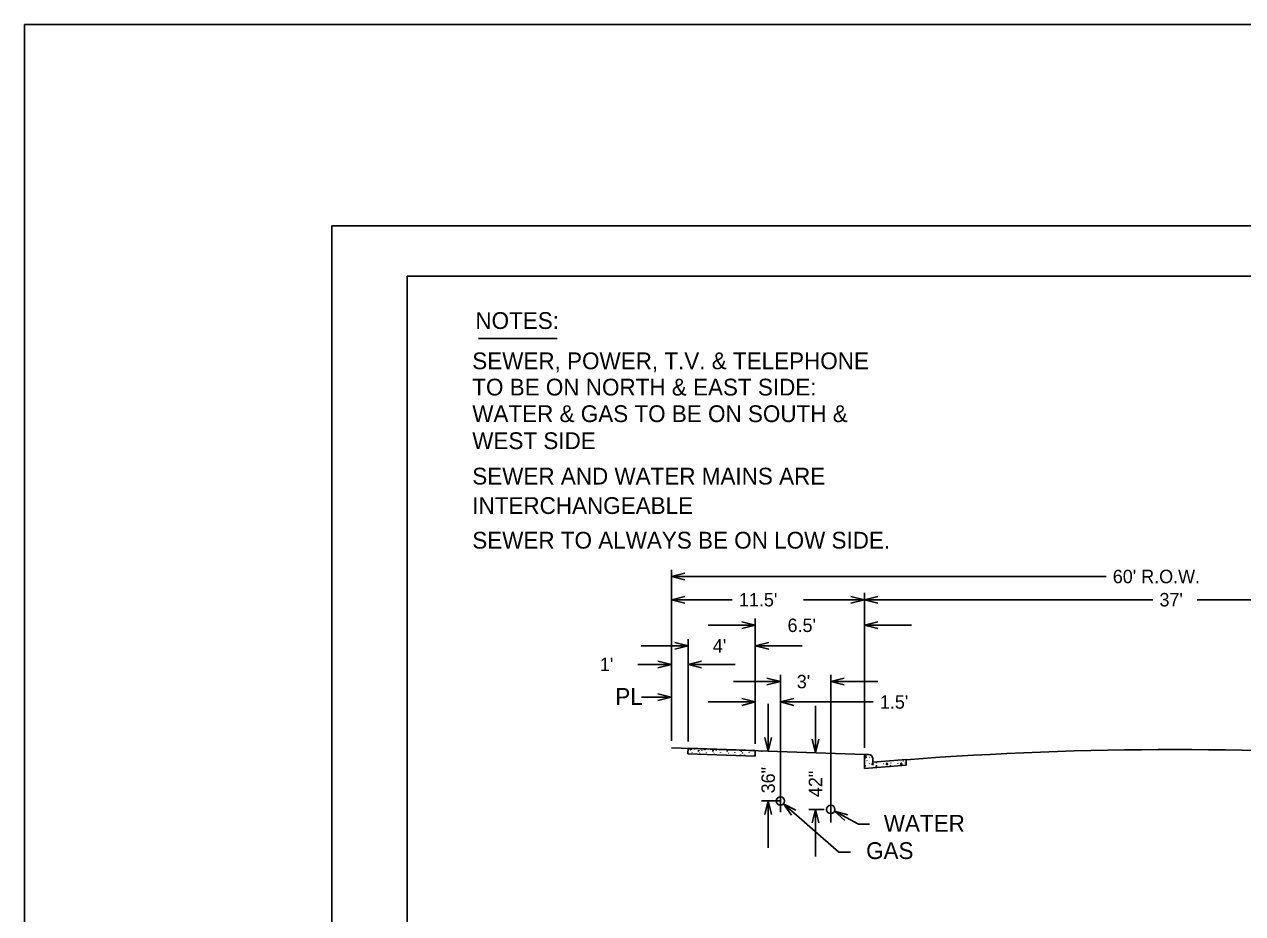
# Model space of a CAD drawing. Extents: x 524397 to 525117, y 3701341 to 3701821.
# Drawn here: x 524396.8 to 524541.9, y 3701715 to 3701821 of the extents above; entities that cross this region are included whole.
import ezdxf

# ---------------------------------------------------------------- set-up
doc = ezdxf.new("R2010")
doc.units = 0
for name, color, linetype in [('Level 1', 7, 'Continuous'), ('Level 11', 7, 'Continuous'), ('Level 9', 7, 'Continuous'), ('Pam batch print border', 7, 'Continuous')]:
    doc.layers.add(name, color=color, linetype=linetype)

msp = doc.modelspace()

# ---------------------------------------------------------------- linework, layer by layer
at = {"layer": 'Level 1'}
for p, q in [((524433.4, 3701796.98), (524433.4, 3701796.98)), ((524442.4, 3701790.98), (524442.4, 3701370.98)), ((524442.4, 3701790.98), (525097.4, 3701790.98))]:
    msp.add_line(p, q, dxfattribs=at)
at = {"layer": 'Level 11'}
for p, q in [((524450.88, 3701783.55), (524460.27, 3701783.55)), ((524473.87, 3701735.57), (524473.87, 3701755.98)), ((524473.87, 3701755.18), (524475.47, 3701755.58)), ((524525.66, 3701755.18), (524473.87, 3701755.18)), ((524475.47, 3701754.78), (524473.87, 3701755.18)), ((524473.87, 3701735.57), (524473.87, 3701753.21)), ((524473.87, 3701752.41), (524475.47, 3701752.81)), ((524481.12, 3701752.41), (524473.87, 3701752.41)), ((524475.47, 3701752.01), (524473.87, 3701752.41)), ((524489.61, 3701752.41), (524496.86, 3701752.41)), ((524495.26, 3701752.81), (524496.86, 3701752.41)), ((524496.86, 3701752.41), (524495.26, 3701752.01)), ((524496.86, 3701734.77), (524496.86, 3701753.21)), ((524496.86, 3701752.41), (524498.46, 3701752.81)), ((524531.22, 3701752.41), (524496.86, 3701752.41)), ((524498.46, 3701752.01), (524496.86, 3701752.41)), ((524536.52, 3701752.41), (524570.88, 3701752.41)), ((524478.26, 3701749.36), (524483.86, 3701749.36)), ((524482.26, 3701749.76), (524483.86, 3701749.36)), ((524483.86, 3701749.36), (524482.26, 3701748.96)), ((524483.86, 3701735.22), (524483.86, 3701750.16)), ((524496.86, 3701734.77), (524496.86, 3701750.16)), ((524496.86, 3701749.36), (524498.46, 3701749.76)), ((524496.86, 3701749.36), (524498.46, 3701749.76)), ((524502.46, 3701749.36), (524496.86, 3701749.36)), ((524498.46, 3701748.96), (524496.86, 3701749.36)), ((524498.46, 3701748.96), (524496.86, 3701749.36)), ((524475.87, 3701735.5), (524475.87, 3701747.71)), ((524483.86, 3701735.22), (524483.86, 3701747.71)), ((524470.27, 3701746.91), (524475.87, 3701746.91)), ((524474.27, 3701747.31), (524475.87, 3701746.91)), ((524475.87, 3701746.91), (524474.27, 3701746.51)), ((524483.86, 3701746.91), (524485.47, 3701747.31)), ((524489.47, 3701746.91), (524483.86, 3701746.91)), ((524485.47, 3701746.51), (524483.86, 3701746.91)), ((524469.87, 3701744.7), (524473.87, 3701744.7)), ((524472.27, 3701745.1), (524473.87, 3701744.7)), ((524473.87, 3701744.7), (524472.27, 3701744.3)), ((524473.87, 3701735.57), (524473.87, 3701745.5)), ((524475.87, 3701735.5), (524475.87, 3701745.5)), ((524475.87, 3701744.7), (524477.47, 3701745.1)), ((524481.47, 3701744.7), (524475.87, 3701744.7)), ((524477.47, 3701744.3), (524475.87, 3701744.7)), ((524486.86, 3701743.45), (524486.86, 3701727.1)), ((524486.86, 3701743.39), (524486.86, 3701743.45)), ((524492.86, 3701743.45), (524492.86, 3701725.84)), ((524481.26, 3701742.65), (524486.86, 3701742.65)), ((524485.26, 3701743.05), (524486.86, 3701742.65)), ((524486.86, 3701742.65), (524485.26, 3701742.25)), ((524492.86, 3701742.65), (524494.47, 3701743.05)), ((524498.47, 3701742.65), (524492.86, 3701742.65)), ((524494.47, 3701742.25), (524492.86, 3701742.65)), ((524492.86, 3701741.98), (524492.86, 3701741.85)), ((524473.86, 3701740.79), (524470.3, 3701740.79)), ((524472.26, 3701741.19), (524473.86, 3701740.79)), ((524473.86, 3701740.79), (524472.26, 3701740.39)), ((524482.26, 3701740.62), (524483.86, 3701740.22)), ((524483.86, 3701735.22), (524483.86, 3701741.02)), ((524486.86, 3701740.82), (524486.86, 3701741.02)), ((524486.86, 3701740.22), (524488.47, 3701740.62)), ((524478.26, 3701740.22), (524483.86, 3701740.22)), ((524483.86, 3701740.22), (524482.26, 3701739.82)), ((524485.4, 3701739.98), (524485.4, 3701734.37)), ((524497.91, 3701740.22), (524486.86, 3701740.22)), ((524488.47, 3701739.82), (524486.86, 3701740.22)), ((524491.04, 3701739.78), (524491.04, 3701734.17)), ((524485.4, 3701734.37), (524485, 3701735.97)), ((524485.8, 3701735.97), (524485.4, 3701734.37)), ((524496.86, 3701733.97), (524473.87, 3701734.77)), ((524475.87, 3701734.7), (524475.85, 3701734.04)), ((524483.86, 3701734.42), (524475.87, 3701734.7)), ((524476.66, 3701734.57), (524476.64, 3701734.6)), ((524478.36, 3701734.57), (524478.34, 3701734.6)), ((524491.04, 3701734.17), (524490.64, 3701735.77)), ((524491.44, 3701735.77), (524491.04, 3701734.17)), ((524475.85, 3701734.04), (524483.86, 3701733.76)), ((524476.33, 3701734.16), (524476.32, 3701734.19)), ((524477.26, 3701734.15), (524477.24, 3701734.13)), ((524477.27, 3701734.16), (524477.26, 3701734.14)), ((524477.51, 3701734.48), (524477.51, 3701734.45)), ((524478.04, 3701734.16), (524478.02, 3701734.19)), ((524478.96, 3701734.15), (524478.94, 3701734.13)), ((524478.97, 3701734.16), (524478.96, 3701734.14)), ((524479.22, 3701734.48), (524479.21, 3701734.45)), ((524479.74, 3701734.16), (524479.72, 3701734.19)), ((524480.66, 3701734.15), (524480.65, 3701734.13)), ((524480.67, 3701734.16), (524480.66, 3701734.14)), ((524480.88, 3701733.89), (524480.87, 3701733.93)), ((524480.92, 3701734.48), (524480.91, 3701734.45)), ((524481.44, 3701734.16), (524481.42, 3701734.19)), ((524481.71, 3701733.84), (524481.71, 3701733.84)), ((524482.36, 3701734.15), (524482.35, 3701734.13)), ((524482.38, 3701734.16), (524482.36, 3701734.14)), ((524482.59, 3701733.89), (524482.57, 3701733.93)), ((524482.62, 3701734.47), (524482.61, 3701734.45)), ((524483.14, 3701734.16), (524483.13, 3701734.19)), ((524483.43, 3701733.81), (524483.41, 3701733.84)), ((524483.86, 3701733.76), (524483.86, 3701734.42)), ((524484.67, 3701734.37), (524484.6, 3701734.37)), ((524490.26, 3701734.17), (524490.24, 3701734.17)), ((524496.86, 3701732.31), (524496.86, 3701733.97)), ((524496.86, 3701733.97), (524497.37, 3701733.97)), ((524497.18, 3701733.2), (524497.16, 3701733.23)), ((524497.37, 3701733.97), (524497.36, 3701733.97)), ((524497.5, 3701733.61), (524497.49, 3701733.64)), ((524497.86, 3701733.51), (524497.86, 3701733.04)), ((524497.86, 3701733.04), (524501.86, 3701733.35)), ((524499.8, 3701733.19), (524499.79, 3701733.17)), ((524499.81, 3701733.19), (524499.8, 3701733.18)), ((524500.58, 3701733.2), (524500.56, 3701733.23)), ((524501.5, 3701733.19), (524501.49, 3701733.17)), ((524501.52, 3701733.2), (524501.5, 3701733.18)), ((524501.86, 3701733.35), (524501.86, 3701732.68)), ((524501.86, 3701732.68), (524496.86, 3701732.31)), ((524497.02, 3701732.63), (524497.01, 3701732.6)), ((524497.46, 3701732.85), (524497.45, 3701732.89)), ((524498.32, 3701732.93), (524498.31, 3701732.97)), ((524498.72, 3701732.63), (524498.71, 3701732.6)), ((524499.17, 3701732.85), (524499.15, 3701732.89)), ((524500.02, 3701732.93), (524500.01, 3701732.97)), ((524500.42, 3701732.63), (524500.41, 3701732.6)), ((524500.87, 3701732.85), (524500.85, 3701732.89)), ((524501.73, 3701732.93), (524501.71, 3701732.97)), ((524486.06, 3701728.42), (524484.6, 3701728.42)), ((524486.86, 3701728.42), (524484.96, 3701728.42)), ((524485, 3701726.82), (524485.4, 3701728.42)), ((524485.4, 3701722.82), (524485.4, 3701728.42)), ((524485.4, 3701728.42), (524485.8, 3701726.82)), ((524488.18, 3701726.73), (524487.24, 3701728.09)), ((524487.24, 3701728.09), (524488.71, 3701727.33)), ((524487.24, 3701728.09), (524493.81, 3701722.31)), ((524492.06, 3701727.42), (524490.24, 3701727.42)), ((524490.64, 3701725.82), (524491.04, 3701727.42)), ((524491.04, 3701721.82), (524491.04, 3701727.42)), ((524491.04, 3701727.42), (524491.44, 3701725.82)), ((524494.53, 3701726.08), (524493.31, 3701727.19)), ((524493.31, 3701727.19), (524494.91, 3701726.78)), ((524493.31, 3701727.19), (524496.18, 3701725.65)), ((524496.18, 3701725.65), (524497.47, 3701725.65)), ((524493.81, 3701722.31), (524495.2, 3701722.31))]:
    msp.add_line(p, q, dxfattribs=at)
for points in [[(524476.15, 3701734.69), (524476.07, 3701734.6), (524476.22, 3701734.53)], [(524476.22, 3701734.53), (524476.2, 3701734.69)], [(524477.8, 3701734.63), (524477.77, 3701734.6), (524477.92, 3701734.53)], [(524477.93, 3701734.53), (524477.91, 3701734.63)], [(524479.54, 3701734.57), (524479.62, 3701734.53)], [(524479.63, 3701734.53), (524479.62, 3701734.57)], [(524477.19, 3701734.34), (524477.15, 3701734.43), (524477.08, 3701734.38), (524477.19, 3701734.34)], [(524478.89, 3701734.34), (524478.85, 3701734.43), (524478.78, 3701734.38), (524478.89, 3701734.34)], [(524480.42, 3701733.88), (524480.41, 3701733.9), (524480.4, 3701733.88)], [(524480.59, 3701734.34), (524480.55, 3701734.43), (524480.48, 3701734.38), (524480.59, 3701734.34)], [(524482.15, 3701733.82), (524482.11, 3701733.9), (524482.08, 3701733.82)], [(524482.29, 3701734.34), (524482.25, 3701734.43), (524482.18, 3701734.38), (524482.29, 3701734.34)], [(524483.86, 3701733.8), (524483.81, 3701733.9), (524483.75, 3701733.77)], [(524497.07, 3701733.57), (524497.04, 3701733.78), (524496.91, 3701733.64), (524497.06, 3701733.57)], [(524497.53, 3701732.36), (524497.53, 3701732.37), (524497.51, 3701732.36)], [(524497.94, 3701732.76), (524497.85, 3701732.94), (524497.77, 3701732.77), (524497.94, 3701732.76)], [(524498.35, 3701732.53), (524498.31, 3701732.62), (524498.23, 3701732.57), (524498.35, 3701732.53)], [(524499.64, 3701732.76), (524499.55, 3701732.94), (524499.47, 3701732.77), (524499.64, 3701732.76)], [(524500.04, 3701732.55), (524500.01, 3701732.62), (524499.94, 3701732.57), (524500.01, 3701732.55)], [(524501.35, 3701732.76), (524501.25, 3701732.94), (524501.18, 3701732.77), (524501.34, 3701732.76)]]:
    msp.add_lwpolyline(points, dxfattribs=at)
for centre in [(524486.86, 3701728.42), (524492.86, 3701727.42)]:
    msp.add_circle(centre, 0.5, dxfattribs=at)
for centre, radius, start, end in [((524533.87, 3701309.32), 425.23, 85.6824, 94.3176), ((524497.36, 3701733.47), 0.494, 3.7079, 90.7668)]:
    msp.add_arc(centre, radius, start, end, dxfattribs=at)
at = {"layer": 'Level 9'}
msp.add_lwpolyline([(524396.79, 3701820.98), (525116.79, 3701820.98), (525116.79, 3701340.98), (524396.79, 3701340.98)], close=True, dxfattribs=at)
at = {"layer": 'Pam batch print border'}
msp.add_lwpolyline([(524433.4, 3701796.98), (525105.4, 3701796.98), (525105.4, 3701364.98), (524433.4, 3701364.98)], close=True, dxfattribs=at)
msp.add_lwpolyline([(524433.4, 3701796.98), (525105.4, 3701796.98), (525105.4, 3701364.98), (524433.4, 3701364.98)], close=True, dxfattribs=at)

# ---------------------------------------------------------------- texts
at = {"layer": 'Level 11'}
for s, height, p in [('NOTES:', 2, (524450.52, 3701784.68)), ('SEWER, POWER, T.V. & TELEPHONE', 2, (524450.15, 3701779.88)), ('TO BE ON NORTH & EAST SIDE:', 2, (524450.15, 3701776.75)), ('WATER & GAS TO BE ON SOUTH &', 2, (524450.15, 3701773.58)), ('WEST SIDE', 2, (524450.15, 3701770.36)), ('SEWER AND WATER MAINS ARE', 2, (524450.15, 3701766.14)), ('INTERCHANGEABLE', 2, (524450.15, 3701762.63)), ('SEWER TO ALWAYS BE ON LOW SIDE.', 2, (524450.15, 3701758.5)), ("60' R.O.W.", 1.601, (524526.46, 3701754.38)), ("11.5'", 1.601, (524481.92, 3701751.61)), ("37'", 1.601, (524532.02, 3701751.61)), ("6.5'", 1.601, (524487.71, 3701748.56)), ("4'", 1.601, (524478.81, 3701746.11)), ("1'", 1.601, (524465.35, 3701743.9)), ("3'", 1.601, (524488.81, 3701741.85)), ('PL', 2, (524467.19, 3701739.88)), ("1.5'", 1.601, (524498.71, 3701739.42)), ('WATER', 2, (524499.18, 3701724.76)), ('GAS', 2, (524497.07, 3701721.5))]:
    msp.add_text(s, height=height, dxfattribs=at).set_placement(p)
for s, p in [('36"', (524486.2, 3701729.33)), ('42"', (524491.84, 3701728.88))]:
    msp.add_text(s, height=1.601, rotation=90, dxfattribs=at).set_placement(p)

doc.saveas('drawing.dxf')
